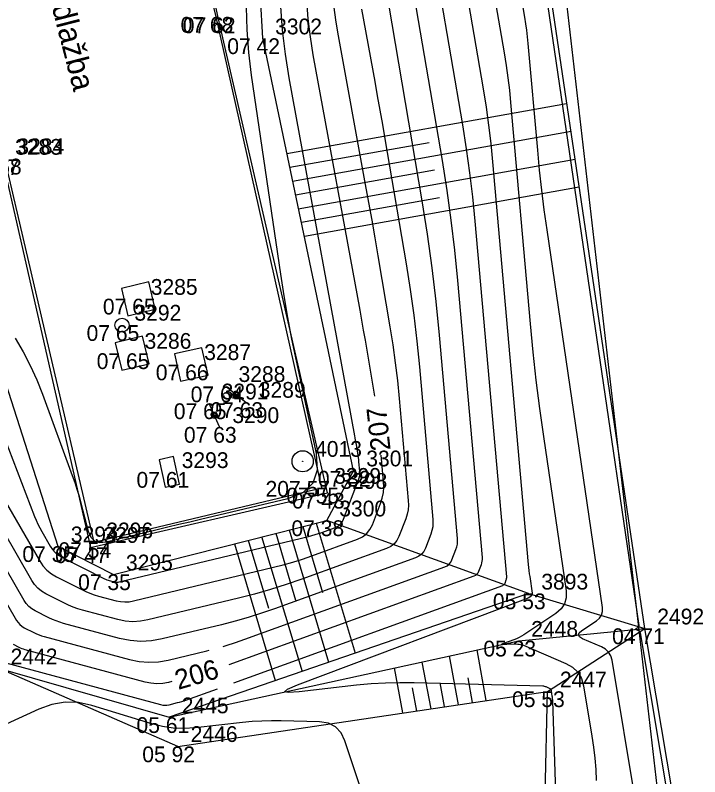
# Model space of a CAD drawing. Extents: x -703403 to -701924, y -1022520 to -1021856.
# Drawn here: x -702441.71 to -702429.54, y -1022345.27 to -1022331.73 of the extents above; entities that cross this region are included whole.
import ezdxf

# ---------------------------------------------------------------- set-up
doc = ezdxf.new("R2010")
doc.units = 0
for name, color, linetype in [('Ex_Contour Labels', 7, 'Continuous'), ('Ex_Major Contours', 7, 'Continuous'), ('Ex_Minor Contours', 7, 'Continuous'), ('Z_bodove_pole', 7, 'Continuous'), ('Z_bodove_pole_cisla', 7, 'Continuous'), ('Z_bodove_pole_vysky', 7, 'Continuous'), ('Z_body', 7, 'Continuous'), ('Z_body_cisla', 7, 'Continuous'), ('Z_body_vysky_redukovane', 7, 'Continuous'), ('Z_chodnik', 7, 'Continuous'), ('Z_hrany_paty', 7, 'Continuous'), ('Z_katastr_hranice', 7, 'Continuous'), ('Z_obruba', 7, 'Continuous'), ('Z_pilire', 7, 'Continuous'), ('Z_popisy', 7, 'Continuous'), ('Z_site_nerozlisene_znaky', 7, 'Continuous'), ('Z_sloupek_kov', 7, 'Continuous'), ('Z_technicke_srafy', 7, 'Continuous'), ('Z_vodni_tok', 7, 'Continuous'), ('Z_zabradli', 7, 'Continuous'), ('Z_zabradli_znaky', 7, 'Continuous')]:
    doc.layers.add(name, color=color, linetype=linetype)

# ---------------------------------------------------------------- blocks, each defined once
blk = doc.blocks.new('POINT_DISPLAY')
blk.add_line((0, 0), (0, 0))
blk = doc.blocks.new('Z666')
for p, q in [((-0.25, 0.13), (-0.25, -0.13)), ((0.25, 0.13), (-0.25, 0.13)), ((0.25, -0.13), (0.25, 0.13)), ((-0.25, -0.13), (0.25, -0.13))]:
    blk.add_line(p, q)
blk = doc.blocks.new('Z608')
for p, q in [((0.25, 0.25), (-0.25, 0.25)), ((-0.25, 0.25), (-0.25, -0.25)), ((0.25, -0.25), (0.25, 0.25)), ((-0.25, -0.25), (0.25, -0.25))]:
    blk.add_line(p, q)
blk = doc.blocks.new('Z15')
blk.add_circle((0, 0), 0.125)
blk = doc.blocks.new('Z530')
for p, q in [((-0.05, 0.03), (-0.03, 0.05)), ((-0.05, -0.03), (-0.05, 0.03)), ((-0.03, 0.05), (0.03, 0.05)), ((-0.03, -0.03), (-0.03, 0.03)), ((-0.03, 0.03), (0.03, 0.03)), ((-0.03, -0.03), (0.03, 0.03)), ((0.03, 0.05), (0.05, 0.03)), ((0.03, 0.03), (0.03, -0.03)), ((0.05, 0.03), (0.05, -0.03)), ((-0.03, -0.05), (-0.05, -0.03)), ((0.03, -0.03), (-0.03, -0.03)), ((0.03, -0.05), (-0.03, -0.05)), ((0.05, -0.03), (0.03, -0.05))]:
    blk.add_line(p, q)
blk = doc.blocks.new('Z101')
for radius in [0.188, 0.0025]:
    blk.add_circle((0, 0), radius)

msp = doc.modelspace()

# ---------------------------------------------------------------- linework, layer by layer
at = {"layer": 'Ex_Major Contours'}
for points in [[(-702434.652, -1022331.197), (-702434.123, -1022334.313), (-702434.039, -1022334.844), (-702433.965, -1022335.375), (-702433.901, -1022335.908), (-702433.849, -1022336.443), (-702433.412, -1022341.373), (-702433.411, -1022341.405), (-702433.414, -1022341.437), (-702433.42, -1022341.468), (-702433.43, -1022341.498), (-702433.476, -1022341.619), (-702433.49, -1022341.647), (-702433.509, -1022341.67), (-702433.532, -1022341.688), (-702433.56, -1022341.702), (-702437.915, -1022343.28)], [(-702430.679, -1022345.733), (-702431.103, -1022343.197), (-702431.126, -1022343.118), (-702431.165, -1022343.052), (-702431.22, -1022342.998), (-702431.291, -1022342.958), (-702431.627, -1022342.814), (-702431.681, -1022342.782), (-702431.701, -1022342.747), (-702431.688, -1022342.708), (-702431.64, -1022342.667), (-702431.381, -1022342.496), (-702431.326, -1022342.449), (-702431.29, -1022342.394), (-702431.273, -1022342.33), (-702431.275, -1022342.257), (-702432.258, -1022335.545), (-702432.307, -1022335.191), (-702432.351, -1022334.837), (-702432.39, -1022334.483), (-702432.424, -1022334.128), (-702432.592, -1022332.23), (-702432.603, -1022332.113), (-702432.617, -1022331.996), (-702432.633, -1022331.88), (-702432.652, -1022331.764), (-702432.731, -1022331.3)], [(-702435.317, -1022338.505), (-702435.334, -1022338.394), (-702435.455, -1022337.683), (-702435.486, -1022337.505), (-702435.517, -1022337.328), (-702435.548, -1022337.15), (-702435.58, -1022336.973), (-702436.412, -1022332.436), (-702436.463, -1022332.115), (-702436.501, -1022331.794), (-702436.525, -1022331.471)], [(-702441.952, -1022340.254), (-702441.278, -1022341.426), (-702441.218, -1022341.516), (-702441.147, -1022341.594), (-702441.065, -1022341.661), (-702440.972, -1022341.716), (-702440.526, -1022341.941), (-702440.453, -1022341.976), (-702440.379, -1022342.006), (-702440.304, -1022342.033), (-702440.227, -1022342.056), (-702439.916, -1022342.139), (-702439.838, -1022342.155), (-702439.761, -1022342.161), (-702439.683, -1022342.157), (-702439.605, -1022342.143), (-702437.117, -1022341.545), (-702436.945, -1022341.501), (-702436.774, -1022341.452), (-702436.605, -1022341.398), (-702436.437, -1022341.34), (-702435.625, -1022341.046), (-702435.537, -1022341.004), (-702435.464, -1022340.947), (-702435.406, -1022340.875), (-702435.362, -1022340.788), (-702435.217, -1022340.409), (-702435.186, -1022340.314), (-702435.167, -1022340.217), (-702435.159, -1022340.118), (-702435.162, -1022340.018), (-702435.203, -1022339.549)], [(-702438.922, -1022343.576), (-702438.982, -1022343.59), (-702439.087, -1022343.609), (-702439.192, -1022343.614), (-702439.296, -1022343.606), (-702439.4, -1022343.585), (-702441.533, -1022343.011), (-702441.56, -1022343.003), (-702441.587, -1022342.993), (-702441.613, -1022342.983), (-702441.639, -1022342.97), (-702441.741, -1022342.919)]]:
    msp.add_lwpolyline(points, dxfattribs=at)
at = {"layer": 'Ex_Minor Contours'}
for points in [[(-702437.822, -1022343.597), (-702433.044, -1022341.866), (-702433.031, -1022341.859), (-702433.02, -1022341.851), (-702433.011, -1022341.84), (-702433.005, -1022341.827), (-702432.983, -1022341.77), (-702432.979, -1022341.756), (-702432.976, -1022341.742), (-702432.974, -1022341.727), (-702432.975, -1022341.712), (-702433.534, -1022335.389), (-702433.577, -1022334.959), (-702433.628, -1022334.53), (-702433.687, -1022334.103), (-702433.755, -1022333.676), (-702434.167, -1022331.254)], [(-702432.083, -1022346.082), (-702432.157, -1022343.92), (-702432.158, -1022343.899), (-702432.16, -1022343.877), (-702432.162, -1022343.856), (-702432.166, -1022343.835), (-702432.182, -1022343.74), (-702432.186, -1022343.726), (-702432.193, -1022343.714), (-702432.202, -1022343.704), (-702432.215, -1022343.697), (-702432.272, -1022343.672), (-702432.287, -1022343.667), (-702432.302, -1022343.663), (-702432.317, -1022343.66), (-702432.332, -1022343.659), (-702434.618, -1022343.599), (-702434.874, -1022343.597), (-702435.131, -1022343.603), (-702435.386, -1022343.619), (-702435.642, -1022343.643), (-702436.662, -1022343.759), (-702436.855, -1022343.773), (-702436.925, -1022343.757), (-702436.87, -1022343.711), (-702436.692, -1022343.635), (-702432.633, -1022342.104), (-702432.62, -1022342.099), (-702432.608, -1022342.093), (-702432.596, -1022342.086), (-702432.584, -1022342.079), (-702432.537, -1022342.048), (-702432.528, -1022342.04), (-702432.521, -1022342.03), (-702432.518, -1022342.018), (-702432.518, -1022342.005), (-702432.561, -1022341.711), (-702432.569, -1022341.658), (-702432.576, -1022341.604), (-702432.581, -1022341.55), (-702432.587, -1022341.496), (-702433.22, -1022334.336), (-702433.252, -1022334.01), (-702433.291, -1022333.686), (-702433.336, -1022333.362), (-702433.388, -1022333.039), (-702433.681, -1022331.31)], [(-702433.195, -1022331.367), (-702433.02, -1022332.401), (-702432.985, -1022332.621), (-702432.954, -1022332.841), (-702432.928, -1022333.062), (-702432.906, -1022333.283), (-702432.558, -1022337.215), (-702432.51, -1022337.718), (-702432.455, -1022338.22), (-702432.392, -1022338.721), (-702432.323, -1022339.221), (-702431.921, -1022341.965), (-702431.918, -1022342.086), (-702431.947, -1022342.193), (-702432.007, -1022342.286), (-702432.1, -1022342.365), (-702432.673, -1022342.744), (-702432.712, -1022342.768), (-702432.751, -1022342.79), (-702432.792, -1022342.809), (-702432.833, -1022342.826), (-702433.051, -1022342.908), (-702433.064, -1022342.914), (-702433.068, -1022342.917), (-702433.063, -1022342.918), (-702433.049, -1022342.917), (-702432.973, -1022342.909), (-702432.955, -1022342.907), (-702432.936, -1022342.906), (-702432.917, -1022342.905), (-702432.898, -1022342.905), (-702432.778, -1022342.909), (-702432.752, -1022342.911), (-702432.727, -1022342.915), (-702432.702, -1022342.922), (-702432.678, -1022342.931), (-702431.926, -1022343.253), (-702431.806, -1022343.321), (-702431.714, -1022343.411), (-702431.649, -1022343.521), (-702431.611, -1022343.654), (-702431.462, -1022344.546), (-702431.432, -1022344.742), (-702431.409, -1022344.94), (-702431.393, -1022345.138), (-702431.383, -1022345.336)], [(-702443.757, -1022334.395), (-702441.365, -1022340.639), (-702441.336, -1022340.708), (-702441.306, -1022340.776), (-702441.272, -1022340.843), (-702441.236, -1022340.908), (-702441.087, -1022341.168), (-702441.046, -1022341.229), (-702440.998, -1022341.282), (-702440.942, -1022341.327), (-702440.879, -1022341.365), (-702440.122, -1022341.748), (-702440.101, -1022341.757), (-702440.08, -1022341.766), (-702440.058, -1022341.774), (-702440.036, -1022341.78), (-702439.947, -1022341.804), (-702439.925, -1022341.809), (-702439.903, -1022341.81), (-702439.881, -1022341.809), (-702439.858, -1022341.805), (-702436.494, -1022340.996), (-702436.435, -1022340.98), (-702436.377, -1022340.964), (-702436.319, -1022340.946), (-702436.261, -1022340.926), (-702436.033, -1022340.843), (-702435.98, -1022340.818), (-702435.936, -1022340.783), (-702435.901, -1022340.74), (-702435.875, -1022340.688), (-702435.607, -1022339.991), (-702435.595, -1022339.953), (-702435.587, -1022339.914), (-702435.584, -1022339.875), (-702435.585, -1022339.835), (-702435.6, -1022339.672), (-702435.604, -1022339.633), (-702435.608, -1022339.594), (-702435.614, -1022339.555), (-702435.62, -1022339.516), (-702435.646, -1022339.36), (-702435.653, -1022339.321), (-702435.66, -1022339.283), (-702435.667, -1022339.244), (-702435.674, -1022339.205), (-702436.84, -1022332.843), (-702436.908, -1022332.421), (-702436.957, -1022331.997), (-702436.988, -1022331.572)], [(-702435.556, -1022331.622), (-702435.32, -1022332.91), (-702435.274, -1022333.164), (-702435.229, -1022333.418), (-702435.184, -1022333.672), (-702435.141, -1022333.927), (-702434.763, -1022336.15), (-702434.691, -1022336.606), (-702434.627, -1022337.063), (-702434.573, -1022337.522), (-702434.527, -1022337.981), (-702434.287, -1022340.695), (-702434.285, -1022340.761), (-702434.29, -1022340.827), (-702434.303, -1022340.891), (-702434.323, -1022340.954), (-702434.419, -1022341.203), (-702434.448, -1022341.261), (-702434.487, -1022341.309), (-702434.535, -1022341.346), (-702434.593, -1022341.374), (-702437.099, -1022342.282), (-702437.332, -1022342.363), (-702437.566, -1022342.437), (-702437.802, -1022342.504), (-702438.041, -1022342.565), (-702439.097, -1022342.819), (-702439.286, -1022342.853), (-702439.476, -1022342.863), (-702439.665, -1022342.848), (-702439.854, -1022342.809), (-702440.851, -1022342.541), (-702440.917, -1022342.521), (-702440.982, -1022342.498), (-702441.046, -1022342.472), (-702441.109, -1022342.443), (-702441.356, -1022342.318), (-702441.415, -1022342.283), (-702441.466, -1022342.241), (-702441.511, -1022342.191), (-702441.549, -1022342.135), (-702443.698, -1022338.399)], [(-702436.045, -1022331.59), (-702436.019, -1022331.81), (-702435.984, -1022332.029), (-702435.487, -1022334.741), (-702435.43, -1022335.057), (-702435.373, -1022335.373), (-702435.318, -1022335.689), (-702435.264, -1022336.006), (-702435.049, -1022337.272), (-702434.998, -1022337.589), (-702434.954, -1022337.907), (-702434.916, -1022338.225), (-702434.885, -1022338.545), (-702434.725, -1022340.357), (-702434.722, -1022340.44), (-702434.728, -1022340.522), (-702434.745, -1022340.602), (-702434.77, -1022340.681), (-702434.891, -1022340.996), (-702434.927, -1022341.068), (-702434.975, -1022341.128), (-702435.036, -1022341.175), (-702435.109, -1022341.21), (-702436.613, -1022341.755), (-702436.891, -1022341.851), (-702437.171, -1022341.94), (-702437.454, -1022342.021), (-702437.739, -1022342.094), (-702439.351, -1022342.481), (-702439.484, -1022342.505), (-702439.618, -1022342.512), (-702439.752, -1022342.502), (-702439.885, -1022342.474), (-702440.51, -1022342.306), (-702440.596, -1022342.281), (-702440.68, -1022342.251), (-702440.763, -1022342.217), (-702440.844, -1022342.179), (-702441.164, -1022342.017), (-702441.24, -1022341.972), (-702441.306, -1022341.917), (-702441.364, -1022341.853), (-702441.414, -1022341.78), (-702442.668, -1022339.6)], [(-702441.709, -1022337.473), (-702441.568, -1022337.712), (-702441.44, -1022337.958), (-702441.325, -1022338.21), (-702441.223, -1022338.468), (-702440.694, -1022339.913), (-702440.651, -1022340.035), (-702440.611, -1022340.157), (-702440.574, -1022340.28), (-702440.54, -1022340.404), (-702440.41, -1022340.902), (-702440.365, -1022341.008), (-702440.298, -1022341.074), (-702440.208, -1022341.102), (-702440.094, -1022341.091), (-702439.187, -1022340.873), (-702438.994, -1022340.827), (-702438.801, -1022340.78), (-702438.608, -1022340.734), (-702438.415, -1022340.688), (-702436.864, -1022340.321), (-702436.59, -1022340.213), (-702436.415, -1022340.044), (-702436.337, -1022339.812), (-702436.357, -1022339.519), (-702436.711, -1022337.872), (-702436.79, -1022337.489), (-702436.862, -1022337.105), (-702436.928, -1022336.719), (-702436.988, -1022336.333), (-702437.508, -1022332.793), (-702437.558, -1022332.392), (-702437.588, -1022331.99), (-702437.599, -1022331.587)], [(-702438.012, -1022342.95), (-702437.96, -1022342.935), (-702437.792, -1022342.882), (-702437.625, -1022342.824), (-702434.077, -1022341.538), (-702434.034, -1022341.517), (-702433.998, -1022341.489), (-702433.969, -1022341.454), (-702433.948, -1022341.411), (-702433.877, -1022341.226), (-702433.862, -1022341.179), (-702433.852, -1022341.132), (-702433.848, -1022341.083), (-702433.85, -1022341.034), (-702434.17, -1022337.417), (-702434.229, -1022336.818), (-702434.3, -1022336.22), (-702434.383, -1022335.623), (-702434.478, -1022335.028), (-702435.071, -1022331.533)], [(-702429.878, -1022347.024), (-702430.6, -1022342.708), (-702430.604, -1022342.697), (-702430.609, -1022342.688), (-702430.617, -1022342.681), (-702430.626, -1022342.675), (-702430.673, -1022342.655), (-702430.68, -1022342.651), (-702430.683, -1022342.646), (-702430.681, -1022342.641), (-702430.674, -1022342.635), (-702430.639, -1022342.612), (-702430.631, -1022342.605), (-702430.626, -1022342.597), (-702430.624, -1022342.589), (-702430.624, -1022342.579), (-702432.242, -1022331.532)], [(-702444.786, -1022337.097), (-702441.685, -1022342.489), (-702441.658, -1022342.529), (-702441.626, -1022342.564), (-702441.59, -1022342.594), (-702441.549, -1022342.618), (-702441.374, -1022342.706), (-702441.33, -1022342.727), (-702441.285, -1022342.746), (-702441.239, -1022342.762), (-702441.192, -1022342.776), (-702439.676, -1022343.184), (-702439.505, -1022343.219), (-702439.334, -1022343.232), (-702439.162, -1022343.223), (-702438.99, -1022343.193), (-702438.302, -1022343.027), (-702438.261, -1022343.017)], [(-702441.874, -1022343.246), (-702439.124, -1022343.986), (-702439.087, -1022343.993), (-702439.05, -1022343.996), (-702439.012, -1022343.994), (-702438.974, -1022343.988), (-702438.824, -1022343.951), (-702438.786, -1022343.942), (-702438.749, -1022343.931), (-702438.712, -1022343.919), (-702438.676, -1022343.907), (-702438.115, -1022343.704)], [(-702435.593, -1022345.411), (-702435.849, -1022344.629), (-702435.917, -1022344.485), (-702436.015, -1022344.382), (-702436.142, -1022344.318), (-702436.299, -1022344.294), (-702436.984, -1022344.276), (-702437.155, -1022344.274), (-702437.326, -1022344.279), (-702437.497, -1022344.289), (-702437.668, -1022344.305), (-702438.508, -1022344.4), (-702438.704, -1022344.413), (-702438.899, -1022344.405), (-702439.091, -1022344.377), (-702439.281, -1022344.329), (-702440.347, -1022344.002), (-702440.586, -1022343.951), (-702440.823, -1022343.944), (-702441.056, -1022343.982), (-702441.286, -1022344.065), (-702444.053, -1022345.338)]]:
    msp.add_lwpolyline(points, dxfattribs=at)
at = {"layer": 'Z_chodnik'}
for p, q in [((-702438.14, -1022331.76), (-702439.25, -1022326.91)), ((-702436.26, -1022340.13), (-702438.14, -1022331.76)), ((-702441.9, -1022334.28), (-702440.31, -1022341.1)), ((-702440.31, -1022341.1), (-702436.26, -1022340.13))]:
    msp.add_line(p, q, dxfattribs=at)
at = {"layer": 'Z_hrany_paty'}
for p, q in [((-702437.31, -1022332.14), (-702437.53, -1022327.91)), ((-702435.7, -1022339.83), (-702437.31, -1022332.14)), ((-702443.36, -1022333.67), (-702440.95, -1022341.17)), ((-702436.17, -1022340.71), (-702435.7, -1022339.83)), ((-702439.96, -1022341.67), (-702436.17, -1022340.71)), ((-702432.59, -1022342.01), (-702436.17, -1022340.71)), ((-702440.95, -1022341.17), (-702439.96, -1022341.67)), ((-702432.59, -1022342.01), (-702438.97, -1022344.21)), ((-702432.59, -1022342.01), (-702430.52, -1022342.63)), ((-702432.76, -1022342.85), (-702430.52, -1022342.63)), ((-702432.25, -1022343.75), (-702430.52, -1022342.63)), ((-702438.97, -1022344.21), (-702432.76, -1022342.85)), ((-702442.01, -1022343.34), (-702438.97, -1022344.21)), ((-702438.82, -1022344.73), (-702442.01, -1022343.34)), ((-702438.82, -1022344.73), (-702432.25, -1022343.75)), ((-702432.32, -1022346.77), (-702432.25, -1022343.75))]:
    msp.add_line(p, q, dxfattribs=at)
at = {"layer": 'Z_katastr_hranice'}
msp.add_line((-702424.63, -1022394.68), (-702432.63, -1022325.24), dxfattribs=at)
at = {"layer": 'Z_obruba'}
for p, q in [((-702438.1, -1022331.77), (-702439.17, -1022326.89)), ((-702436.16, -1022340.22), (-702438.1, -1022331.77)), ((-702441.94, -1022334.29), (-702440.37, -1022341.19)), ((-702440.37, -1022341.19), (-702436.16, -1022340.22))]:
    msp.add_line(p, q, dxfattribs=at)
at = {"layer": 'Z_technicke_srafy'}
for p, q in [((-702436.88, -1022334.19), (-702431.91, -1022333.3)), ((-702436.78, -1022334.68), (-702431.83, -1022333.79)), ((-702436.83, -1022334.43), (-702434.35, -1022333.99)), ((-702436.68, -1022335.17), (-702431.76, -1022334.29)), ((-702436.73, -1022334.92), (-702434.26, -1022334.48)), ((-702436.57, -1022335.66), (-702431.69, -1022334.78)), ((-702436.62, -1022335.41), (-702434.17, -1022334.97)), ((-702436.6, -1022340.82), (-702436.25, -1022341.99)), ((-702436.36, -1022340.76), (-702435.67, -1022343.07)), ((-702437.08, -1022340.94), (-702436.73, -1022342.13)), ((-702436.84, -1022340.88), (-702436.14, -1022343.23)), ((-702437.57, -1022341.06), (-702437.21, -1022342.27)), ((-702437.33, -1022341), (-702436.61, -1022343.4)), ((-702437.81, -1022341.13), (-702437.09, -1022343.56)), ((-702433.83, -1022343.99), (-702433.99, -1022343.12)), ((-702433.34, -1022343.91), (-702433.5, -1022343.01)), ((-702434.32, -1022344.06), (-702434.48, -1022343.23)), ((-702434.82, -1022344.13), (-702434.97, -1022343.33)), ((-702433.58, -1022343.95), (-702433.66, -1022343.51)), ((-702434.08, -1022344.02), (-702434.16, -1022343.6)), ((-702434.57, -1022344.1), (-702434.65, -1022343.69))]:
    msp.add_line(p, q, dxfattribs=at)
at = {"layer": 'Z_vodni_tok'}
for p, q in [((-702430.52, -1022342.63), (-702432.24, -1022331.05)), ((-702429.75, -1022347.23), (-702430.52, -1022342.63))]:
    msp.add_line(p, q, dxfattribs=at)
at = {"layer": 'Z_zabradli'}
for p, q in [((-702437.96, -1022338.33), (-702437.61, -1022338.61)), ((-702438.08, -1022339.05), (-702438.26, -1022338.63))]:
    msp.add_line(p, q, dxfattribs=at)

# ---------------------------------------------------------------- block references
at = {"layer": 'Z_bodove_pole'}
msp.add_blockref('Z101', (-702436.6, -1022339.66), dxfattribs=at)
at = {"layer": 'Z_body'}
for p in [(-702438.14, -1022331.76), (-702438.1, -1022331.77), (-702437.31, -1022332.14), (-702439.52, -1022336.77), (-702439.81, -1022337.24), (-702439.63, -1022337.74), (-702438.58, -1022337.94), (-702437.96, -1022338.33), (-702438.26, -1022338.63), (-702437.61, -1022338.61), (-702438.08, -1022339.05), (-702436.6, -1022339.66), (-702438.97, -1022339.85), (-702435.7, -1022339.83), (-702436.26, -1022340.13), (-702436.16, -1022340.22), (-702436.17, -1022340.71), (-702440.31, -1022341.1), (-702440.95, -1022341.17), (-702440.37, -1022341.19), (-702439.96, -1022341.67), (-702432.59, -1022342.01), (-702430.52, -1022342.63), (-702432.76, -1022342.85), (-702432.25, -1022343.75), (-702438.97, -1022344.21), (-702438.82, -1022344.73)]:
    msp.add_blockref('POINT_DISPLAY', p, dxfattribs=at)
at = {"layer": 'Z_pilire', "rotation": -77.39999999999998}
msp.add_blockref('Z666', (-702438.97, -1022339.85), dxfattribs=at)
at = {"layer": 'Z_site_nerozlisene_znaky'}
for p, rotation in [((-702439.52, -1022336.77), 13.5), ((-702439.63, -1022337.74), 13.5), ((-702438.58, -1022337.94), 12.6)]:
    msp.add_blockref('Z608', p, dxfattribs=dict(at, rotation=rotation))
at = {"layer": 'Z_sloupek_kov'}
msp.add_blockref('Z15', (-702439.81, -1022337.24), dxfattribs=at)
at = {"layer": 'Z_zabradli_znaky'}
for p, rotation in [((-702437.78, -1022338.47), -38.699999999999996), ((-702438.17, -1022338.84), -66.80000000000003)]:
    msp.add_blockref('Z530', p, dxfattribs=dict(at, rotation=rotation))

# ---------------------------------------------------------------- texts
at = {"layer": 'Ex_Contour Labels'}
for s, rotation, p in [('207', 96.1991, (-702435.037, -1022339.457)), ('206', 16.3642, (-702438.811, -1022343.725))]:
    msp.add_text(s, height=0.35, rotation=rotation, dxfattribs=at).set_placement(p)
at = {"layer": 'Z_bodove_pole_cisla'}
msp.add_text('4013', height=0.28, dxfattribs=at).set_placement((-702436.38, -1022339.58))
at = {"layer": 'Z_bodove_pole_vysky'}
msp.add_text('207,57', height=0.28, dxfattribs=at).set_placement((-702437.26, -1022340.29))
at = {"layer": 'Z_body_cisla'}
for s, p in [('3302', (-702437.09, -1022332.07)), ('3283', (-702441.71, -1022334.21)), ('3284', (-702441.67, -1022334.2)), ('3285', (-702439.3, -1022336.7)), ('3292', (-702439.59, -1022337.16)), ('3286', (-702439.41, -1022337.66)), ('3287', (-702438.35, -1022337.86)), ('3288', (-702437.74, -1022338.25)), ('3289', (-702437.38, -1022338.53)), ('3291', (-702438.04, -1022338.56)), ('3290', (-702437.85, -1022338.98)), ('3301', (-702435.47, -1022339.75)), ('3293', (-702438.75, -1022339.78)), ('3299', (-702436.04, -1022340.06)), ('3298', (-702435.93, -1022340.15)), ('3300', (-702435.95, -1022340.64)), ('3294', (-702440.72, -1022341.1)), ('3297', (-702440.14, -1022341.11)), ('3296', (-702440.09, -1022341.03)), ('3295', (-702439.74, -1022341.6)), ('3893', (-702432.36, -1022341.94)), ('2492', (-702430.3, -1022342.56)), ('2448', (-702432.54, -1022342.78)), ('2442', (-702441.79, -1022343.27)), ('2447', (-702432.03, -1022343.68)), ('2445', (-702438.75, -1022344.14)), ('2446', (-702438.59, -1022344.65))]:
    msp.add_text(s, height=0.28, dxfattribs=at).set_placement(p)
at = {"layer": 'Z_body_vysky_redukovane'}
for s, p in [('07 68', (-702438.77, -1022332.04)), ('07 62', (-702438.73, -1022332.05)), ('07 42', (-702437.94, -1022332.42)), ('07 67', (-702442.57, -1022334.57)), ('07 68', (-702442.53, -1022334.56)), ('07 65', (-702440.15, -1022337.05)), ('07 65', (-702440.44, -1022337.52)), ('07 65', (-702440.26, -1022338.02)), ('07 66', (-702439.21, -1022338.22)), ('07 64', (-702438.59, -1022338.61)), ('07 65', (-702438.89, -1022338.91)), ('07 63', (-702438.24, -1022338.89)), ('07 63', (-702438.71, -1022339.33)), ('07 61', (-702439.553, -1022340.13)), ('07 32', (-702436.33, -1022340.11)), ('07 55', (-702436.89, -1022340.41)), ('07 43', (-702436.79, -1022340.5)), ('07 38', (-702436.8, -1022340.99)), ('07 54', (-702440.94, -1022341.38)), ('07 35', (-702441.58, -1022341.45)), ('07 47', (-702441, -1022341.47)), ('07 35', (-702440.59, -1022341.95)), ('05 53', (-702433.22, -1022342.29)), ('04 71', (-702431.103, -1022342.91)), ('05 23', (-702433.39, -1022343.13)), ('05 53', (-702432.88, -1022344.03)), ('05 61', (-702439.553, -1022344.49)), ('05 92', (-702439.45, -1022345.01))]:
    msp.add_text(s, height=0.28, dxfattribs=at).set_placement(p)
at = {"layer": 'Z_popisy'}
msp.add_text('zámková dlažba', height=0.4, rotation=284.4, dxfattribs=at).set_placement((-702441.63, -1022329.36))

doc.saveas('drawing.dxf')
